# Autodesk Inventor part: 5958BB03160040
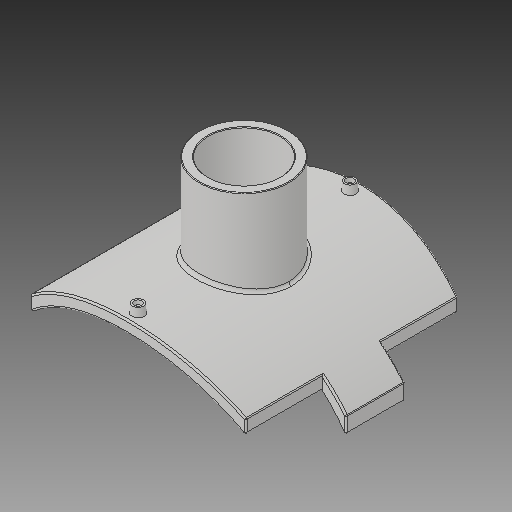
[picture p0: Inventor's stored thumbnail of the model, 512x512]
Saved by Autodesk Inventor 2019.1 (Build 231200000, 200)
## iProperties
Created: 2017-10
Part Number: 5958BB03160040
Material: Generic
Description: PLASSON BRANCH SADDLE 10''-16''IPS x 10''-14''DIPS
Document SubType Name: Modeling
Designer: KIM
Density: 1 g/cm^3
Appearance: Default
Author: KIM
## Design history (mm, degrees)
derived "5958B-1.ipt"
feature "Solid1::5958B-1.ipt"
tag "TaggingFeature1"
body "Solid1"
other parameters: "d0" = 404.6, "d1" = 14.986, "d2" = 274.32, "d3" = 299.974, "d4" = 0, "d5" = 304.8, "d6" = 74.9935, "d7" = 0, "d8" = 134.9883, "d10" = 0, "d11" = 2.023, "d12" = 227.9, "d13" = 14, "d14" = 134.9883, "d16" = 5 deg, "d18" = 4, "d19" = 14, "d20" = 0, "d21" = 3, "d22" = 0, "d23" = 322.188, "d24" = 114.1, "d25" = 16, "d26" = 91.28, "d28" = 0, "d29" = 9.6, "d31" = 0, "d32" = 83.9216, "d33" = 0, "d34" = 4.046, "d35" = 0.8092, "d_" = 404.6, "d_1" = 114.1, "B_" = 304.8, "H_" = 119.888, "L_" = 299.974, "x_" = 14.986, "D_" = 16, "H1" = 104.902
